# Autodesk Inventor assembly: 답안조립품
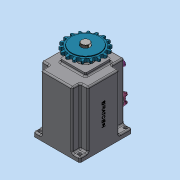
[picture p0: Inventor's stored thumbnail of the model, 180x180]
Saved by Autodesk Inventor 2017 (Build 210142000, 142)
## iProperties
Part Number: 답안조립품
Material: 일반
Document SubType Name: Assembly
Designer: MRC
Author: MRC
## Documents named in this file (16)
- C:\Users\MRC\Desktop\720212V1015\답안조립품.iam
- C:\Users\MRC\Desktop\720212V1015\멈춤나사 M3.ipt
- C:\Users\MRC\Desktop\720212V1015\메인 축.ipt
- C:\Users\MRC\Desktop\720212V1015\베어링 608.ipt
- C:\Users\MRC\Desktop\720212V1015\베어링 6003.ipt
- C:\Users\MRC\Desktop\720212V1015\본체.ipt
- C:\Users\MRC\Desktop\720212V1015\볼트 M4 x 10.ipt
- C:\Users\MRC\Desktop\720212V1015\부시.ipt
- C:\Users\MRC\Desktop\720212V1015\상부 캡.ipt
- C:\Users\MRC\Desktop\720212V1015\서브 축.ipt
- C:\Users\MRC\Desktop\720212V1015\스프로킷.ipt
- C:\Users\MRC\Desktop\720212V1015\슬라이더.ipt
- C:\Users\MRC\Desktop\720212V1015\오일 실 8 x 22 x 7.ipt
- C:\Users\MRC\Desktop\720212V1015\오일 실 17 x 32 x 8.ipt
- C:\Users\MRC\Desktop\720212V1015\커버.ipt
- C:\Users\MRC\Desktop\720212V1015\키 5 x 5.ipt
